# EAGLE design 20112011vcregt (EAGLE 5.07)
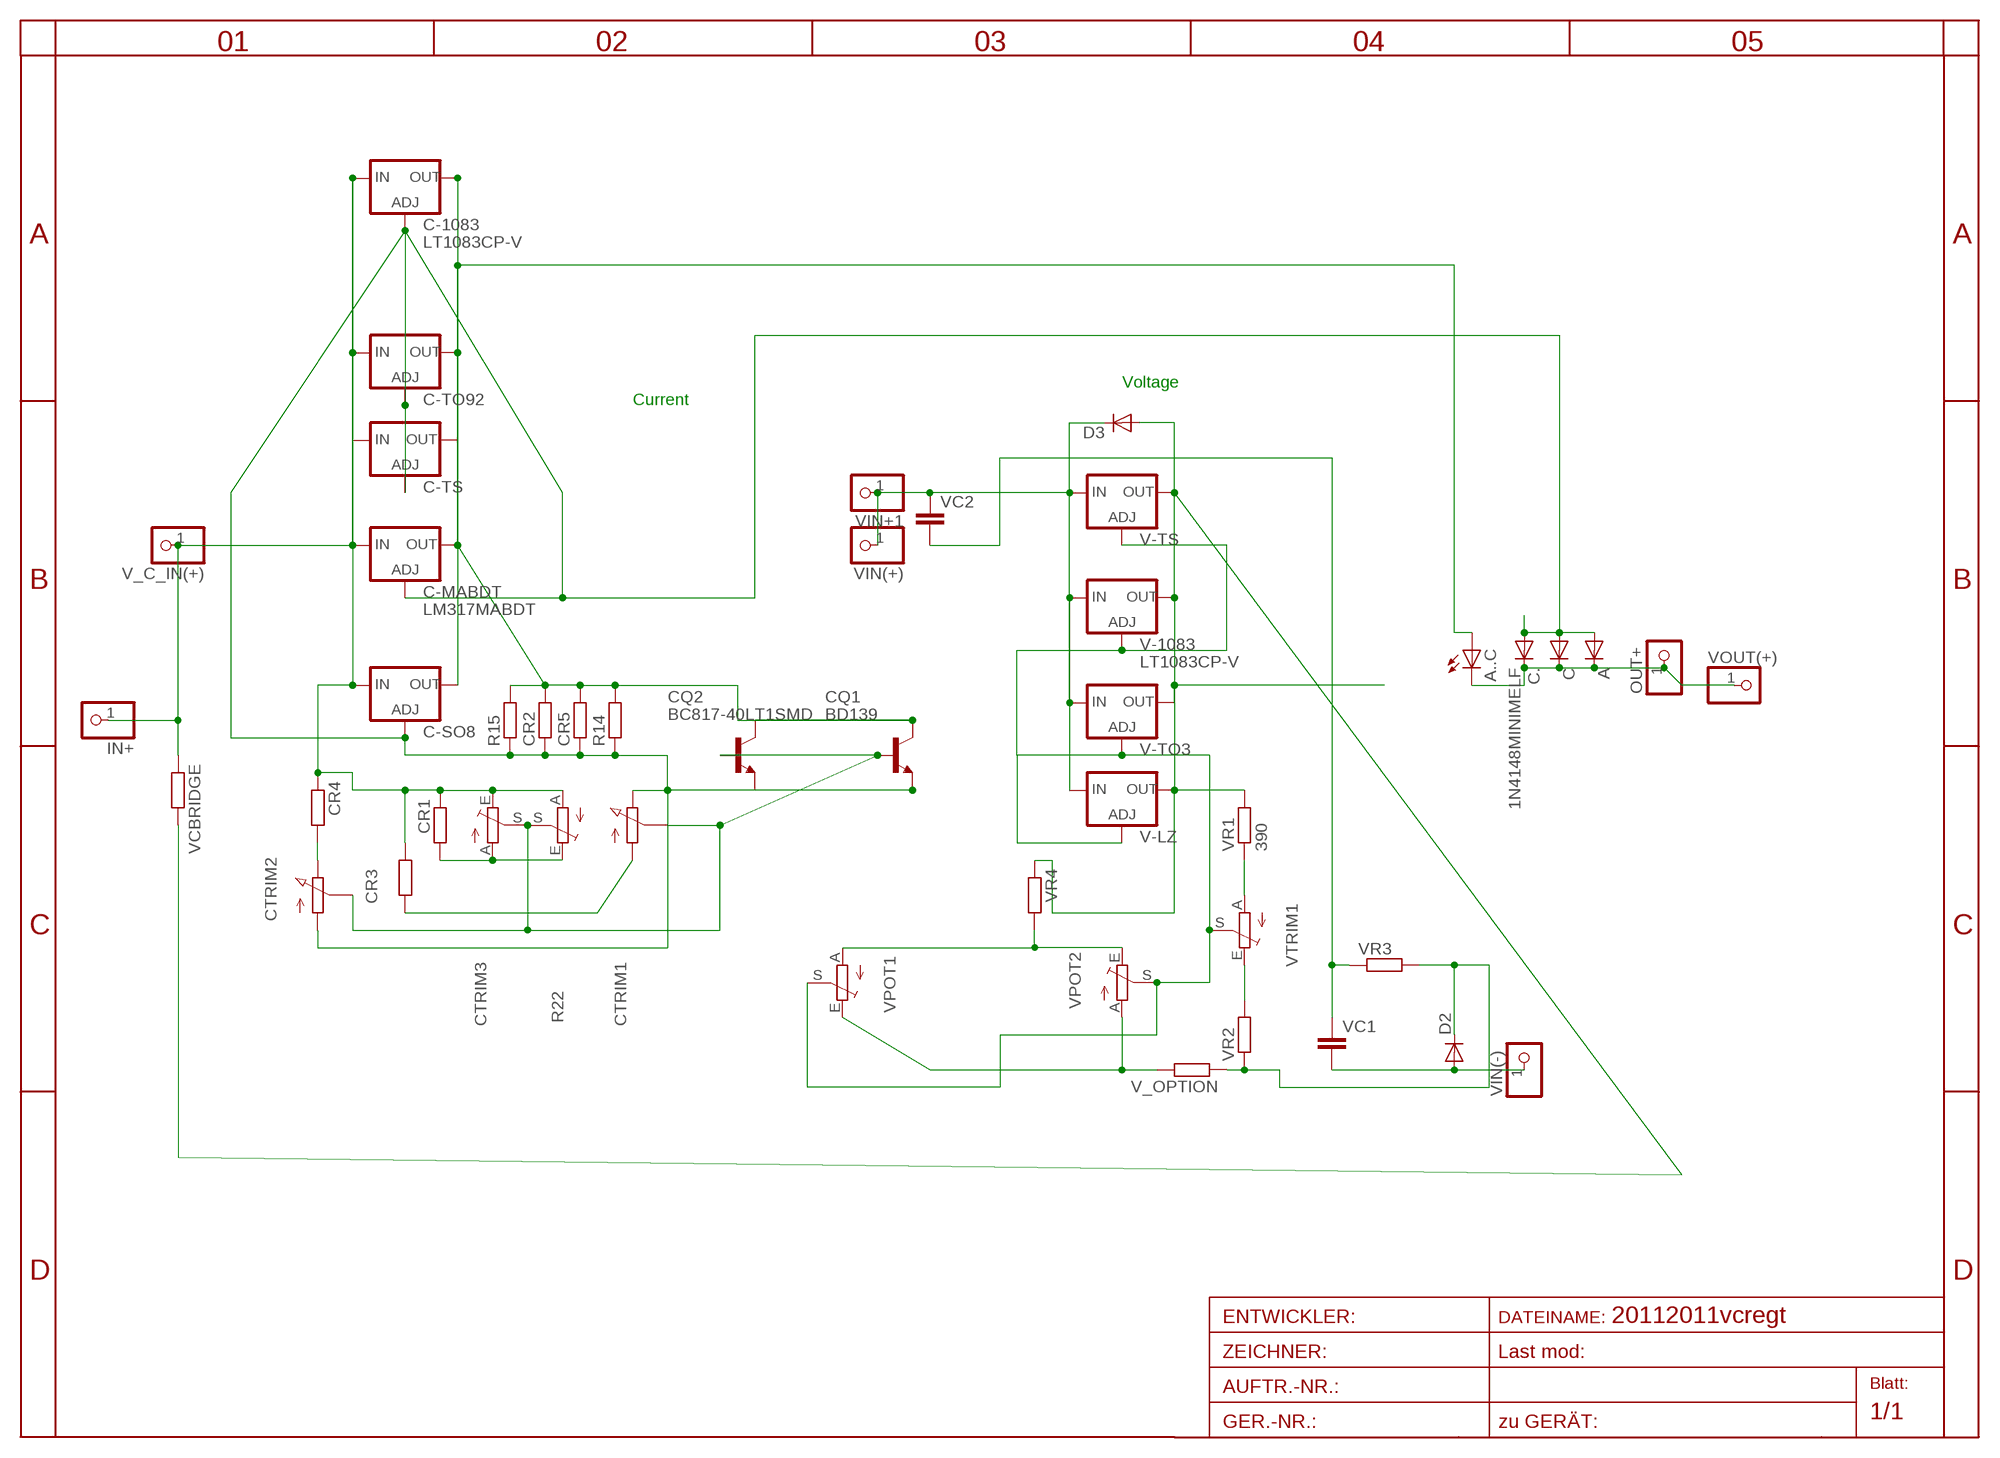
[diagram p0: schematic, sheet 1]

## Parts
A  DIODE-TO220V  [TO220ACS]
A..C  LED3MM  [LED3MM]
C  DIODE-SMB  [SMB]
C-1083  LT1083CP-V  [TO247S]
C-MABDT  LM317MABDT  [DPACK]
C-SO8  LM317LM-OUTPIN7  [SO08]
C-TO92  LM317LZ  [317L]
C-TS  LM317TS  [317TS]
C.  1N4148MINIMELF  [MINIMELF]
CQ1  BD139  [TO126V]
CQ2  BC817-40LT1SMD  [SOT23-BEC]
CR1  R-EU_0207/15  [0207/15]
CR2  R-EU_R1206  [R1206]
CR3  R-EU_R1206  [R1206]
CR4  R-EU_R1206  [R1206]
CR5  R-EU_R1206  [R1206]
CTRIM1  PC25  [PC25]
CTRIM2  PC25  [PC25]
CTRIM3  TRIM_EU-S64W  [S64W]
D2  DIODE-MINIMELF  [MINIMELF]
D3  DIODE-MINIMELF  [MINIMELF]
IN+  PINHD-1X1  [1X01]
OUT+  PINHD-1X1  [1X01]
R14  R-EU_R1206  [R1206]
R15  R-EU_R1206  [R1206]
R22  TRIM_EU-RAND160  [RANDL]
V-1083  LT1083CP-V  [TO247S]
V-LZ  LM317LZ  [317L]
V-TO3  LM317-TO3  [TO3-K02]
V-TS  LM317TS  [317TS]
V_C_IN(+)  PINHD-1X11MM6  [1X1MM8]
V_OPTION  R-EU_R0402  [R0402]
VC1  C-EU050-025X075  [C050-025X075]
VC2  C-EU050-025X075  [C050-025X075]
VCBRIDGE  R-EU_R0402  [R0402]
VIN(+)  PINHD-1X11MM6  [1X1MM8]
VIN(-)  PINHD-1X1  [1X01]
VIN+1  PINHD-1X1  [1X01]
VOUT(+)  PINHD-1X11MM6  [1X1MM8]
VPOT1  TRIM_EU-RAND160  [RANDL]
VPOT2  TRIM_EU-S64W  [S64W]
VR1  390  R-EU_0207/12  [0207/12]
VR2  R-EU_0204/7  [0204/7]
VR3  R-EU_0204/5  [0204/5]
VR4  R-EU_0207/10  [0207/10]
VTRIM1  TRIM_EU-EVND_H  [EVND8AA]

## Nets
ADJ2: V-1083.1(ADJ) V-LZ.1(ADJ) V-TO3.2(ADJ) V-TS.1(ADJ) VPOT1.S VPOT2.S VTRIM1.S
ADJUST: A.A C-1083.1(ADJ) C-MABDT.1(ADJ) C-SO8.4(ADJ) C-TO92.1(ADJ) C-TS.1(ADJ) C..A C.A CQ1.3(E) CQ2.E CR2.1 CR5.1 CTRIM1.E CTRIM2.A R14.1 R15.1
B1: CQ1.1(B) CQ2.B CTRIM1.S CTRIM2.S CTRIM3.S R22.S
IN+1: D3.C V-1083.3(IN) V-LZ.3(IN) V-TO3.1(IN) V-TS.3(IN) VC2.1 VIN(+).1 VIN+1.1
IN-: D2.A VC1.2 VIN(-).1
INPUT+: C-1083.3(IN) C-MABDT.3(IN) C-SO8.1(IN) C-TO92.3(IN) C-TS.3(IN) CR1.2 CR3.2 CR4.1 CTRIM3.E IN+.1 R22.A V_C_IN(+).1 VCBRIDGE.1
MINUS: CR1.1 CTRIM3.A R22.E
N$1: V_OPTION.2 VPOT1.E VPOT2.A
N$2: VPOT1.A VPOT2.E VR4.2
N$3: VR2.2 VTRIM1.E
N$4: VR1.1 VTRIM1.A
N$5: CR3.1 CTRIM1.A
N$6: CR4.2 CTRIM2.E
N$7: VC1.1 VC2.2 VR3.1
OUT1: A..C.A C-1083.2(OUT) C-MABDT.4(OUT) C-SO8.7(OUT) C-TO92.2(OUT) C-TS.2(OUT) CQ1.2(C) CQ2.C CR2.2 CR5.2 R14.2 R15.2
OUT2: D3.A V-1083.2(OUT) V-LZ.2(OUT) V-TO3.3(OUT) V-TS.2(OUT) VCBRIDGE.2 VR1.2 VR4.1
OUT+: A..C.K(C) A.C C..C C.C OUT+.1 VOUT(+).1
VIRT-: D2.C V_OPTION.1 VR2.1 VR3.2

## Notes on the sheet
- Voltage
- Current

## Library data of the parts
A C D2 D3 = diode:DIODE-: DIODE
A..C = led:LED: LED
C-1083 V-1083 = linear-technology-2:LT1083*: 7.5A Low Dropout Positive Adjustable Regulators
C-MABDT = v-reg:LM317?*: 500 mA Adjustable Output Positive Voltage Regulator Source: http://www.onsemi.co.jp .. LM317M-D.PDF
C-SO8 C-TO92 V-LZ = v-reg-3:LM317L: Adjustable Voltage Regulator, 1.2V to 37V, 100mA
C-TS V-TS = v-reg:LM317TS: VOLTAGE REGULATOR
C. = diode-1:1N4148: DIODE
CQ1 = transistor-npn:BD139*: NPN Transistor
CQ2 = transistor-npn:BC817*: NPN Transistor
CR1-CR5 R14 R15 V_OPTION VCBRIDGE VR1-VR4 = rcl-2:R-EU_: RESISTOR, European symbol
CTRIM1 CTRIM2 = pot-vitrohm:PC25: VITROHM POTENTIOMETER
CTRIM3 R22 VPOT1 VPOT2 VTRIM1 = pot:TRIM_EU-: POTENTIOMETER
IN+ OUT+ VIN(-) VIN+1 = pinhead(2):PINHD-1X1: PIN HEADER
V-TO3 = v-reg:LM317-TO3: VOLTAGE REGULATOR
V_C_IN(+) VIN(+) VOUT(+) = pinhead:PINHD-1X1: PIN HEADER
VC1 VC2 = rcl:C-EU: CAPACITOR, European symbol

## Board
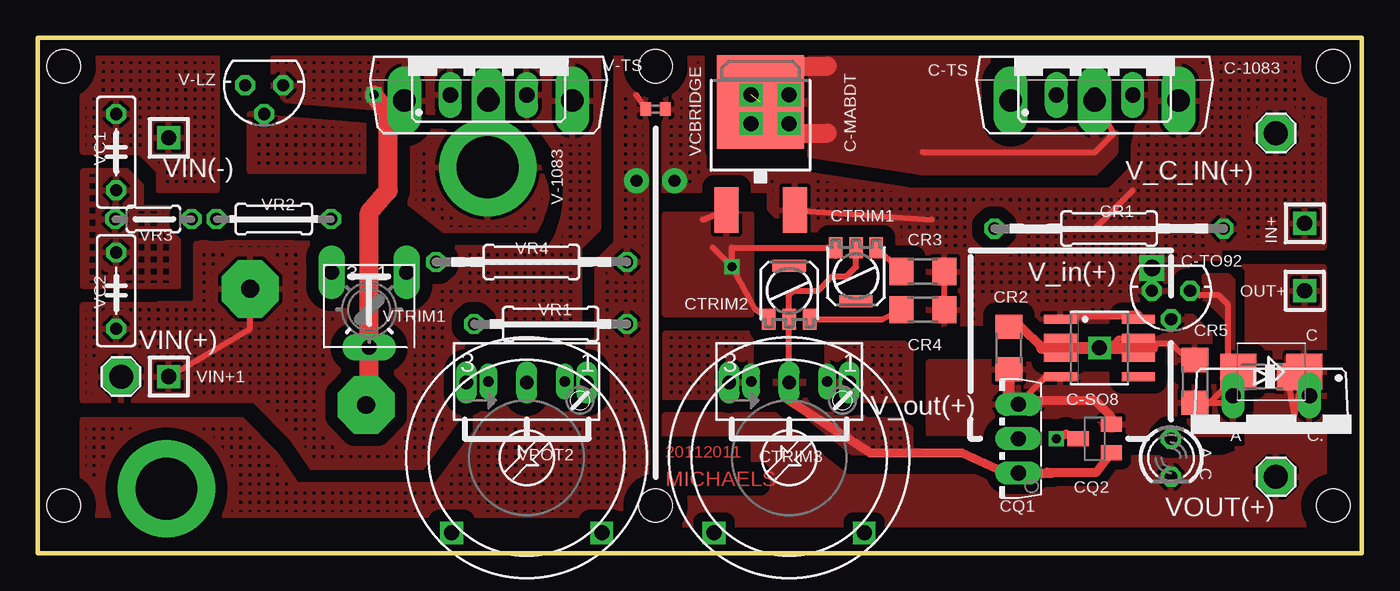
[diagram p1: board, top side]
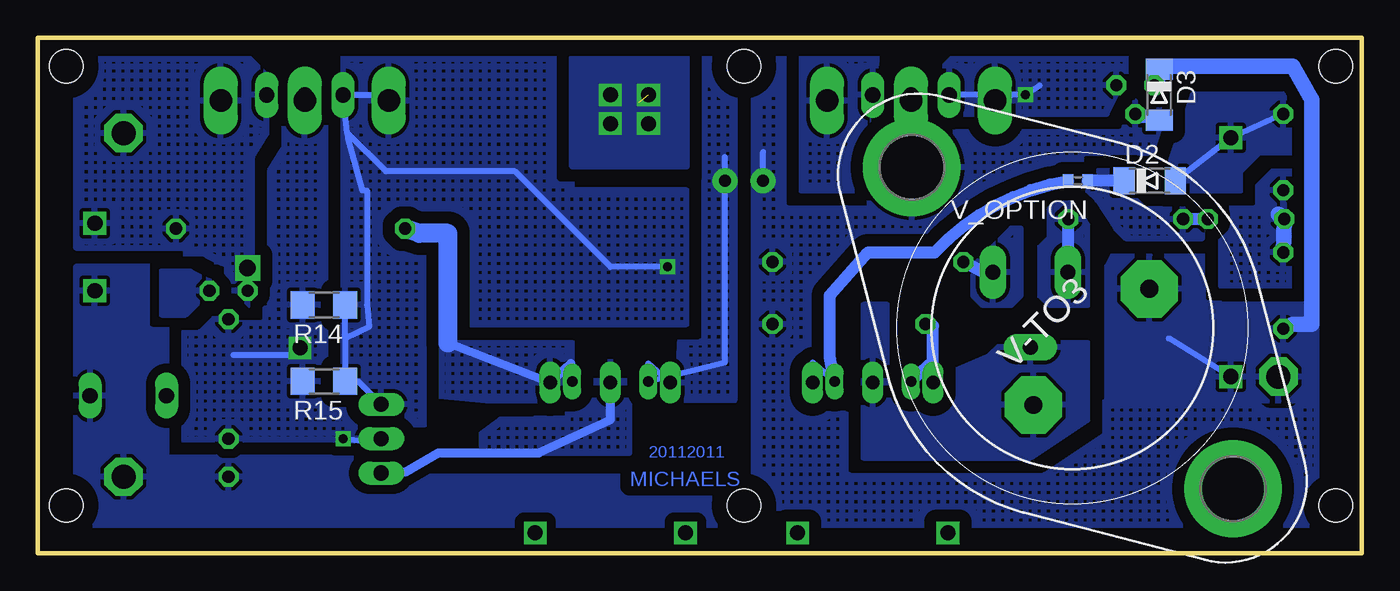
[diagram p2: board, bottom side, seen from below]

Size 88.1 x 34.29 mm. Coordinates in mm from the lower left corner, seen from the top.
Outline: 0,0 88.1,0 88.1,34.29 0,34.29 0,0
Copper layers (1*16): Top 0.035mm / dielectric 1.5mm / Bottom 0.035mm
Design rules "default": minimum track width 10mil, minimum drill 24mil, track to track 8mil, track to pad 8mil, pad to pad 8mil, via to via 8mil, smd to smd 8mil, copper to edge 40mil, drill to drill 8mil, minimum pad ring 10mil, minimum via ring 8mil, stop-mask expansion 4mil, vias tented up to drill 0mil, thermal gap 10mil
Holes 2.2 mm at 86.2,32.38 86.2,3.17 86.2,3.17 41.11,32.38 41.11,3.17 1.74,32.38 1.74,3.17

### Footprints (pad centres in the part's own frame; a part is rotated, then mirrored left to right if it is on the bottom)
TO220ACS = drill 1.016 long: A 2.54,-2.54; C -2.54,-2.54
LED3MM = drill 0.813 octagon: A -1.27,0; K 1.27,0
SMB = smd 2.4 x 2.4: A 2.2,0; C -2.2,0
TO247S = drill 1.499 long: 1 -5.588,-2.921; 2 0,-2.921; 3 5.588,-2.921
DPACK = smd 1.6 x 3: 1 -2.28,-4.8; 3 2.28,-4.8 | smd 5.8 x 6.2: 4 0,2.38
SO08 = smd 0.6 x 2.2: 1 -1.905,-2.6; 2 -0.635,-2.6; 3 0.635,-2.6; 4 1.905,-2.6; 5 1.905,2.6; 6 0.635,2.6; 7 -0.635,2.6; 8 -1.905,2.6
317L = drill 0.813 octagon: 1 -1.27,0; 2 0,1.905; 3 1.27,0
317TS = drill 1.016 long: 1 -2.54,-2.54; 2 0,-2.54; 3 2.54,-2.54
MINIMELF = smd 1.4 x 1.8: A 1.7,0; C -1.7,0
TO126V = drill 1.016 long: 1 -2.286,-1.27; 2 0,-1.27; 3 2.286,-1.27
SOT23-BEC = smd 1 x 1.4: B -0.95,-1.1; C 0,1.1; E 0.95,-1.1
0207/15 = drill 0.813 octagon: 1 -7.62,0; 2 7.62,0
R1206 = smd 1.6 x 1.803: 1 -1.422,0; 2 1.422,0
PC25 = smd 2.2 x 0.8: 4 0,1.65 | smd 0.9 x 1.4: A -1.35,-1.9; E 1.35,-1.9; S 0,-1.9
S64W = drill 0.7 long: A 2.54,1.27; E -2.54,1.27; S 0,1.27
1X01 = drill 1.016 square: 1 0,0
RANDL = drill 0.9 long: A -4,5; E 4,5; S 0,5 | drill 1 square: P$1 -5,-5; P$2 5,-5
TO3-K02 = drill 1.194 pad 3.81 octagon: 1 -1.778,-5.461; 2 -1.778,5.461 | drill 4.115 pad 6.477 round: 3 15.113,0; 3@ -15.113,0
1X1MM8 = drill 1.6 pad 2.54 octagon: 1 0,0
R0402 = smd 0.7 x 0.9: 1 -0.65,0; 2 0.65,0
C050-025X075 = drill 0.813 octagon: 1 -2.54,0; 2 2.54,0
0207/12 = drill 0.813 octagon: 1 -6.35,0; 2 6.35,0
0204/7 = drill 0.813 octagon: 1 -3.81,0; 2 3.81,0
0204/5 = drill 0.813 octagon: 1 -2.54,0; 2 2.54,0
0207/10 = drill 0.813 octagon: 1 -5.08,0; 2 5.08,0
EVND8AA = drill 1 pad 1.778 long: A -2.5,-2.5; E 2.5,-2.5; S 0,2.5

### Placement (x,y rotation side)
A  82.07,7.94 180 top
A..C  75.4,6.35 270 top
C  82.07,12.06 180 top
C-1083  70.32,33.02 0 top
C-MABDT  48.1,27.62 0 top
C-SO8  70.64,13.65 270 top
C-TO92  75.4,17.46 180 top
C-TS  70.32,33.02 0 top
C.  81.43,11.75 180 top
CQ1  63.97,7.62 90 top
CQ2  70.32,7.62 90 top
CR1  71.27,21.59 0 top
CR2  64.61,13.65 90 top
CR3  58.89,18.73 0 top
CR4  58.89,16.19 180 top
CR5  76.99,11.43 90 top
CTRIM1  54.45,18.41 180 top
CTRIM2  50,17.46 0 top
CTRIM3  50,10.16 0 top
D2  14.12,24.77 0 bottom
D3  13.49,30.48 270 bottom
IN+  84.29,21.94 0 top
OUT+  84.29,17.46 90 top
R14  69.05,16.51 180 bottom
R15  69.05,11.43 180 bottom
R22  50,6.35 0 top
V-1083  30,33.02 0 top
V-LZ  15.07,31.11 180 top
V-TO3  19.26,14.98 135 bottom
V-TS  30,33.02 0 top
V_C_IN(+)  82.39,27.94 0 top
V_OPTION  18.88,24.77 180 bottom
VC1  5.23,26.67 90 top
VC2  5.23,17.46 90 top
VCBRIDGE  41.11,29.53 180 top
VIN(+)  5.55,11.75 0 top
VIN(-)  8.72,27.62 0 top
VIN+1  8.72,11.75 0 top
VOUT(+)  82.39,5.08 0 top
VPOT1  32.54,6.35 0 top
VPOT2  32.54,10.16 0 top
VR1  32.86,19.37 0 top
VR2  15.71,22.22 0 top
VR3  7.71,22.22 0 top
VR4  34.12,15.24 180 top
VTRIM1  22.06,16.19 180 top

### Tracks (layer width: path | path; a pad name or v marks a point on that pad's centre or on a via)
ADJ2  (via drill 0.6)
  Top 1.27: V-TO3.2 22.06,9.86 22.06,13.33 22.06,22.66 23.33,24.13 23.33,29.21 v22.38,30.48
  Bottom 0.406: 24.06,29.75 V-1083.1 24.79,30.48 V-TS.1 | 24.06,29.75 23.52,29.21 | 24.06,29.75 23.33,30.48 v22.38,30.48 21.43,31.11
  pour Bottom (isolate 0.813, hatched): 15.71,31.75 15.71,33.02 27.14,33.02 28.41,31.75 28.41,30.48 27.14,29.21 16.98,29.21
  pour Bottom (isolate 0.813, rank 3): 18.25,13.97 23.96,13.97 24.92,13.02 31.58,10.16 31.58,16.51 33.17,16.51 33.17,6.35 22.06,6.35 18.25,8.89
  pour Top (isolate 0.813, hatched): 15.71,33.02 27.14,33.02 28.41,31.75 28.41,30.48 27.14,29.21 15.71,30.16
ADJUST  (via drill 0.6)
  Top 0.406: C-SO8.4 67.08,11.75 CQ1.3 | CQ1.3 65.18,9.84 | CQ1.3 64.61,10.54 | 44.25,22.19 C-MABDT.1 | CTRIM2.A 47.77,16.2 v46.19,19.05 | CTRIM1.E 53.1,19.77 52.54,20.32 46.19,20.32 v46.19,19.05 | v46.19,19.05 44.92,20.32 | 71.42,8.89 71.42,8.42 | C..A 77.47,9.53 CR5.1 79.06,10.01 79.21,10.16 79.21,16.51 78.58,17.14 77.31,17.14 C-TO92.1 | A.A C.A
  Top 0.61: CQ2.E 71.42,8.89 71.42,9.06 70.32,10.16 65.49,10.16 CQ1.3
  Top 0.813: 64.61,10.54 CR2.1
  Bottom 0.406: R15.1 67.78,11.28 | 67.5,27.97 67.46,27.62 66.51,24.13 66.19,24.13 66.19,16.51 66.04,15.07 67.63,14.29 | 67.5,27.97 C-TS.1 65.11,30.48 C-1083.1 | 67.63,14.29 R15.1 | 67.63,14.29 R14.1 | v46.19,19.05 50,19.05 56.35,25.4 64.93,25.4 67.5,27.97 | R15.1 66.76,11.43 CQ1.3
  pour Top (isolate 0.813): 41.75,22.54 47.46,22.54 47.46,15.88 41.75,15.88
  pour Top (isolate 0.813, rank 2): 59.27,12.7 59.27,7.94 79.53,7.94 79.53,18.1 79.21,18.41 77.62,18.41 77.62,11.11 74.13,11.43 71.59,11.43 70.32,12.7
  pour Bottom (isolate 0.61): 76.67,17.46 76.67,18.1 77.94,18.73 79.84,18.73 79.84,15.88 78.26,15.88
  pour Bottom (isolate 0.813, rank 3, hatched): 52.54,33.02 67.78,33.02 67.78,11.43 63.97,8.57 62.38,8.57 62.38,21.59 60.16,21.59 60.16,15.24 44.92,15.24 44.92,24.13 52.54,24.13
B1
  Top 0.406: 67.53,5.33 67.14,5.4 | CTRIM3.S CTRIM2.S 50,17.14 50.32,17.46 51.91,17.46 52.86,18.41 53.81,18.41 54.45,19.05 CTRIM1.S | R22.S 50,10.16 | 64.99,5.08 CQ1.1
  Top 0.61: CQ2.B 70.47,5.4 67.14,5.4 | CQ1.1 67.53,5.33 | 64.99,5.08 61.49,6.67 55.4,6.67 50,10.16
  Bottom 0.406: CQ1.1 63.65,5.4
  Bottom 0.61: 63.65,5.4 61.43,6.67 54.76,6.67 50,8.89 CTRIM3.S
  pour Bottom (isolate 0.813, rank 6, hatched): 48.73,12.7 51.27,12.7 55.08,8.89 57.3,8.89 58.57,7.94 58.57,6.67 48.73,6.67
  pour Top (isolate 0.813, rank 6, hatched): 48.73,12.7 51.27,12.7 55.08,8.89 57.3,8.89 58.57,7.94 58.57,6.67 52.86,6.67 50,8.26 48.73,9.53
IN+1
  Top 0.406: V-TO3.1 14.14,14.94 VIN+1.1
  Bottom 0.406: VIN+1.1 12.85,14.29 | 4.6,15.24 VC2.1 | D3.C 13.42,32.18 13.42,31.88
  Bottom 1.016: V-LZ.3 13.42,31.88 13.17,32.38 4.6,32.38 3.33,30.16 3.33,27.3 3.33,15.24 4.6,15.24
  pour Bottom (isolate 0.813, hatched): 32.22,33.02 37.3,33.02 37.3,24.13 33.49,24.13
  pour Top (isolate 0.813, rank 3, hatched): 3.01,16.51 8.09,16.51 10.63,20.64 16.98,20.64 28.41,20.32 34.12,20.32 arc90 32.22,29.21 32.22,33.02 37.3,33.02 37.3,21.59 36.03,20.32 36.03,15.24 28.41,15.24 28.09,9.21 25.55,5.71 18.25,5.71 16.98,7.62 14.44,10.16 3.01,10.16
  pour Bottom (isolate 0.813, rank 4): 16.98,19.05 16.98,10.16 3.01,10.16 3.01,16.51 9.36,16.51 10.63,17.78 10.63,21.59 15.71,21.59
IN-
  Bottom 0.406: VC1.2 VIN(-).1 D2.A
  pour Bottom (isolate 0.813, rank 2): 4.28,30.48 11.26,30.48 12.85,25.72 12.85,24.13 8.09,24.13 8.09,25.4 6.82,26.67 4.28,26.67
  pour Top (isolate 0.813, hatched): 3.01,33.02 11.9,33.02 11.9,24.13 8.09,24.13 8.09,25.4 6.82,26.67 3.01,26.67
INPUT+  (via drill 0.8 pad 1.68, 1.1 pad 1.68)
  Top 0.406: CR4.1 CR3.2 | C-SO8.1 68.73,15.56 69.05,15.88 | C-MABDT.3 59.49,22.19 | 69.05,21.59 70.32,21.59 72.86,24.13
  Top 0.61: 69.05,15.88 73.18,15.88
  Bottom 0.406: R22.A 47.46,12.62 CTRIM3.E 42.38,12.7 v42.38,24.77 42.38,26.35
  other vias: 74.13,18.97
  pour Top (isolate 0.813, rank 5, hatched): 74.13,33.02 85.56,33.02 85.56,20.32 78.58,20.32 78.58,15.56 60.16,15.24 56.35,15.24 48.73,22.86 48.73,24.13 41.11,24.13 41.75,33.02 44.29,33.02 44.29,25.4 72.86,25.4 72.86,26.67
  pour Bottom (isolate 0.813, rank 2, hatched): 74.45,33.02 85.56,33.34 85.56,20.32 78.26,20.32 78.26,19.05 76.67,16.19 73.81,16.51 73.81,26.35 72.86,27.94 72.86,31.75 74.13,33.02
  pour Bottom (isolate 0.813, rank 5, hatched): 41.75,33.02 41.75,10.16 45.55,10.16 44.29,33.02
  pour Top (isolate 0.813, rank 5, hatched): 41.75,14.61 41.75,10.16 47.46,10.16 47.46,14.61
MINUS
  Bottom 0.406: 52.62,12.62 CTRIM3.A
  Bottom 0.61: 60.8,13.97 R22.E 52.62,12.62
  Bottom 1.27: CR1.1 62.7,21.27 60.8,21.27 60.8,13.97
  pour Bottom (isolate 0.813, rank 4, hatched): 52.54,13.97 61.43,13.97 61.43,10.48 58.26,10.16 53.49,10.16 52.54,11.11
  pour Top (isolate 0.813, rank 4, hatched): 52.54,13.97 57.62,13.97 58.26,13.33 58.26,10.16 53.49,10.16 52.54,11.11
N$1
  Bottom 0.406: VPOT2.A 36.54,12.7 VPOT1.E
  Bottom 0.813: VPOT2.A 35.4,13.02 35.4,17.14 32.86,20 28.41,20 arc38 V_OPTION.2
N$2
  Bottom 0.813: VPOT2.E 28.62,12.7 VPOT1.A 28.54,15.11 VR4.2
N$3
  Bottom 0.813: VR2.2 19.52,18.73 VTRIM1.E
  pour Bottom (isolate 0.813, rank 2, hatched): 18.25,23.5 20.15,23.5 20.79,22.86 20.79,20.95 21.43,20.32 21.43,17.14 20.79,16.51 18.25,16.51
N$4
  Bottom 0.813: VTRIM1.A 25.2,18.69 VR1.1
  pour Bottom (isolate 0.813, rank 3, hatched): 22.7,21.59 23.33,21.59 25.87,19.05 25.87,17.14 25.23,16.51 23.33,16.51 22.7,17.14
N$5
  Top 0.406: CTRIM1.A 56.84,19.36 CR3.1
N$6
  Top 0.406: 56.98,16.19 CR4.2 56.2,15.56 52.62,15.56 CTRIM2.E
N$7
  Bottom 1.016: VC2.2 VR3.1 5.55,22.54
  pour Bottom (isolate 0.813, rank 3, hatched): 4.28,25.4 4.28,17.78 9.36,17.78 9.36,25.4
  pour Top (isolate 0.813, rank 2, hatched): 3.01,25.4 3.01,17.78 9.36,17.78 9.36,25.4
OUT1  (via drill 0.6, 1)  (1 unrouted)
  Top 0.406: C-MABDT.4 49.84,29.37 | v70.64,13.65 71.59,13.97 71.91,14.29 C-SO8.7 | CR2.2 65.41,15.07 | C-1083.2 71.59,27.94 70.32,26.67 58.89,26.67 | CR5.2 76.84,12.53 75.4,13.97 73.81,13.97 73.5,13.65
  Top 0.61: CQ2.C 68.42,7.94 v67.78,7.62 | 65.41,15.07 66.83,13.65
  Top 0.813: 74.13,13.65 73.5,13.65 v70.64,13.65 66.83,13.65
  Top 1.27: 50.64,27.94 52.54,27.94 | 50,32.38 52.54,32.38
  Bottom 0.406: 65.56,7.3 v67.78,7.62 | 75.08,13.17 71.12,13.17 v70.64,13.65
  other vias: 47.46,30.48 50,30.48 50,28.57 47.46,28.57
  pour Bottom (isolate 0.813, rank 5, hatched): 69.05,30.16 72.54,30.8 73.5,23.5 73.5,15.56 77.31,15.56 78.58,14.92 78.89,7.3 65.88,7.3
  pour Top (isolate 0.813, rank 3): 50.64,33.02 72.86,33.02 71.59,30.48 71.59,26.67 70.32,25.4 58.89,25.4 50.64,26.67
  pour Bottom (isolate 0.813, rank 2): 44.92,33.02 44.92,25.72 52.54,25.72 52.54,33.02
  pour Top (isolate 0.813): 74.77,15.88 76.67,15.88 77.94,14.61 77.94,12.7 74.13,12.7
OUT2  (via drill 0.8 pad 1.68)
  Top 0.406: VCBRIDGE.2 39.84,30.48
  Bottom 0.406: v39.84,24.77 39.84,26.67 | V-TO3.3 29.94,30.04 V-1083.2 V-TS.2 | D3.A 15.07,28.78 V-LZ.2
  pour Bottom (isolate 0.813, rank 4, hatched): 15.07,30.16 17.3,29.21 30.95,29.21 33.49,26.67 33.49,25.4 34.76,24.13 37.3,24.13 37.3,33.02 40.48,33.02 40.48,1.91 3.01,1.91 3.01,10.16 16.98,10.16 21.43,6.35 33.49,6.35 33.49,8.89 36.67,10.16 35.4,18.1 29.68,20.64 arc38 22.06,25.4 arc16 13.49,26.67 11.9,29.21
  pour Top (isolate 0.813, rank 4, hatched): 14.12,29.21 30.95,29.21 33.49,26.67 33.49,25.4 34.76,24.13 37.3,24.13 37.3,33.02 40.48,33.02 40.48,2.54 3.01,2.54 3.01,8.89 15.71,8.89 17.61,5.71 25.87,5.71 28.41,10.16 36.67,10.16 36.67,20.32 36.98,21.59 36.03,21.59 34.76,20.32 28.09,20.64 22.06,25.4 14.12,25.4
OUT+
  Top 0.406: C..C 83.63,9.21 C.C
  pour Top (isolate 0.61, rank 3): 80.16,19.05 85.56,19.05 85.56,2.54 84.92,1.91 42.38,1.91 41.75,2.54 41.75,9.21 49.05,9.21 50.64,7.62 53.81,5.08 70.32,5.08 70.32,6.35 78.89,6.35 79.84,6.67 79.84,10.48 82.39,10.48 82.39,13.65 80.16,13.65 80.16,14.61 79.84,14.92 79.84,18.73
  pour Bottom (isolate 0.61, rank 2): 79.53,19.05 85.56,19.05 85.56,2.54 84.92,1.91 42.38,1.91 42.06,6.03 48.41,6.03 49.05,5.08 63.34,5.08 63.34,6.03 64.29,6.35 79.53,6.35
VIRT-
  Bottom 0.813: 15.71,24.65 D2.C V_OPTION.1 | VR3.2 VR2.1
  pour Bottom (isolate 0.813, hatched): 15.71,25.4 17.61,25.4 18.25,24.77 18.25,24.13 17.61,23.5 16.34,21.59 15.71,20.95 10.63,20.95 10.63,22.86 14.44,22.86 15.07,23.5

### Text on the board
Top: 20112011 | MICHAELS
Bottom: 20112011 | MICHAELS
tNames: V_in(+) | V_out(+)
tTest: output | plus | C schottky diode A | minus | LM317T | resistor | LM317T | resistor | plus | trimmer | A silicon diode C | regulated | A LED C | transistor ECB | resistor | potentiometer | resistor | potentiometer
